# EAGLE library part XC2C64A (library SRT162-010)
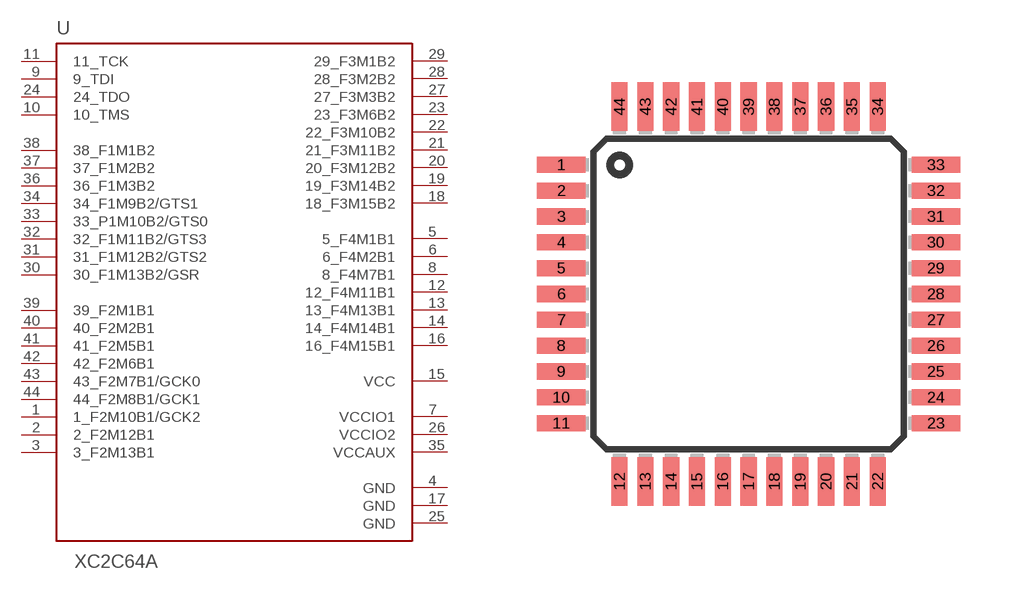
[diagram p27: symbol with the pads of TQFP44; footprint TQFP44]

Designator prefix U

## XC2C64A  [TQFP44]
1  1_F2M10B1/GCK2
2  2_F2M12B1
3  3_F2M13B1
4  GND  pwr
5  5_F4M1B1
6  6_F4M2B1
7  VCCIO1  pwr
8  8_F4M7B1
9  9_TDI
10  10_TMS
11  11_TCK  in
12  12_F4M11B1
13  13_F4M13B1
14  14_F4M14B1
15  VCC  pwr
16  16_F4M15B1
17  GND  pwr
18  18_F3M15B2
19  19_F3M14B2
20  20_F3M12B2
21  21_F3M11B2
22  22_F3M10B2
23  23_F3M6B2
24  24_TDO
25  GND  pwr
26  VCCIO2  pwr
27  27_F3M3B2
28  28_F3M2B2
29  29_F3M1B2
30  30_F1M13B2/GSR
31  31_F1M12B2/GTS2
32  32_F1M11B2/GTS3
33  33_P1M10B2/GTS0
34  34_F1M9B2/GTS1
35  VCCAUX  pwr
36  36_F1M3B2
37  37_F1M2B2
38  38_F1M1B2
39  39_F2M1B1
40  40_F2M2B1
41  41_F2M5B1
42  42_F2M6B1
43  43_F2M7B1/GCK0
44  44_F2M8B1/GCK1

## Footprint TQFP44 (pad centres in mm)
smd 1.5 x 0.5: 1 -5.8,4; 2 -5.8,3.2; 3 -5.8,2.4; 4 -5.8,1.6; 5 -5.8,0.8; 6 -5.8,0; 7 -5.8,-0.8; 8 -5.8,-1.6; 9 -5.8,-2.4; 10 -5.8,-3.2; 11 -5.8,-4; 23 5.8,-4; 24 5.8,-3.2; 25 5.8,-2.4; 26 5.8,-1.6; 27 5.8,-0.8; 28 5.8,0; 29 5.8,0.8; 30 5.8,1.6; 31 5.8,2.4; 32 5.8,3.2; 33 5.8,4
smd 0.5 x 1.5: 12 -4,-5.8; 13 -3.2,-5.8; 14 -2.4,-5.8; 15 -1.6,-5.8; 16 -0.8,-5.8; 17 0,-5.8; 18 0.8,-5.8; 19 1.6,-5.8; 20 2.4,-5.8; 21 3.2,-5.8; 22 4,-5.8; 34 4,5.8; 35 3.2,5.8; 36 2.4,5.8; 37 1.6,5.8; 38 0.8,5.8; 39 0,5.8; 40 -0.8,5.8; 41 -1.6,5.8; 42 -2.4,5.8; 43 -3.2,5.8; 44 -4,5.8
